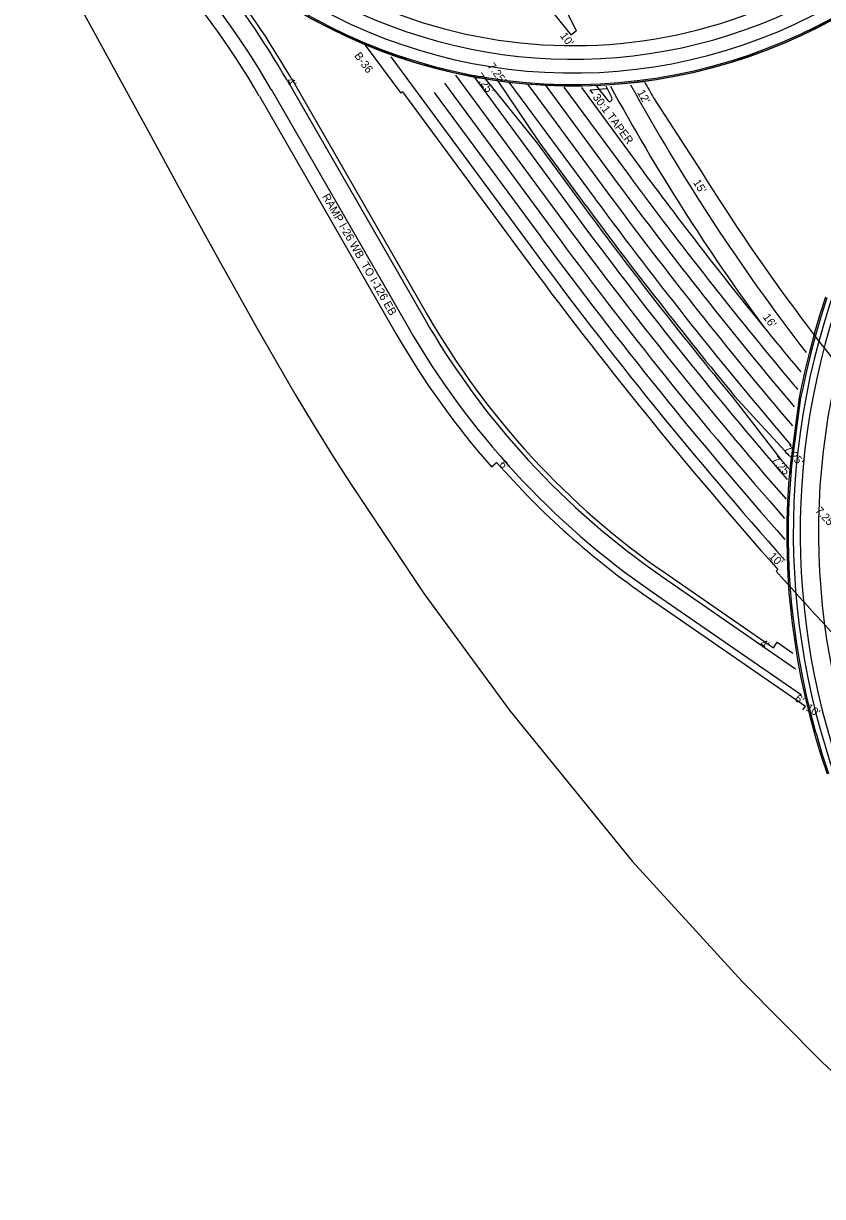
# Model space of a CAD drawing. Extents: x -5665 to 1997148, y 4 to 812485.
# Drawn here: x 1970730 to 1971429, y 795072 to 796097 of the extents above; entities that cross this region are included whole.
import ezdxf

# ---------------------------------------------------------------- set-up
doc = ezdxf.new("R2010")
doc.units = 0
for name, color, linetype in [('BR_CONCRETE', 7, 'Continuous'), ('RD_EX_RailRoad', 7, 'Continuous'), ('RD_PD_ALT1_TrvlWay', 7, 'Continuous'), ('RD_PD_Final_LnLine', 7, 'Continuous'), ('RD_PD_MedBWall', 7, 'Continuous'), ('RD_PD_PaveShd', 7, 'Continuous'), ('RD_SHT_TX', 7, 'Continuous')]:
    doc.layers.add(name, color=color, linetype=linetype)

msp = doc.modelspace()

# ---------------------------------------------------------------- linework, layer by layer
at = {"layer": 'BR_CONCRETE'}
for points in [[(1971431.6, 795857.9), (1971426.5, 795842), (1971421.8, 795826), (1971417.5, 795809.9), (1971413.6, 795793.7), (1971410.1, 795777.4), (1971408.6, 795770.1), (1971400.6, 795710.7), (1971399.3, 795694.8), (1971398.4, 795678.8), (1971397.8, 795662.9), (1971397.7, 795647), (1971398, 795631), (1971398.7, 795615.1), (1971399.7, 795599.2), (1971400.7, 795588.6), (1971402.5, 795572.7), (1971404.7, 795556.8), (1971407.2, 795541), (1971410.2, 795525.2), (1971413.6, 795509.5), (1971417.3, 795494), (1971421.5, 795478.5), (1971422.6, 795474.3), (1971427.6, 795457.7), (1971433, 795441.2)], [(1971432.8, 795857.4), (1971427.8, 795841.6), (1971423.1, 795825.6), (1971418.8, 795809.5), (1971414.9, 795793.4), (1971411.4, 795777.1), (1971409.9, 795769.9), (1971401.9, 795710.5), (1971400.6, 795694.7), (1971399.7, 795678.8), (1971399.1, 795662.9), (1971399, 795647), (1971399.3, 795631), (1971400, 795615.1), (1971401, 795599.3), (1971402, 795588.7), (1971403.8, 795572.8), (1971405.9, 795557), (1971408.5, 795541.2), (1971411.5, 795525.5), (1971414.8, 795509.8), (1971418.6, 795494.3), (1971422.7, 795478.8), (1971423.9, 795474.7), (1971428.8, 795458.1), (1971434.2, 795441.6)]]:
    msp.add_lwpolyline(points, dxfattribs=at)
for radius, start in [(473.1, 234.9869), (472, 234.9869), (473.3, 235.2092)]:
    msp.add_arc((1971210.8, 796516), radius, start, 298.9233, dxfattribs=at)
at = {"layer": 'RD_EX_RailRoad'}
msp.add_lwpolyline([(1970768.6, 796133), (1970840.2, 796002.2), (1970871.3, 795945), (1970902.8, 795888.1), (1970934.6, 795831.3), (1970952.2, 795800.2), (1970967.8, 795773.4), (1970983.8, 795746.9), (1971000.1, 795720.5), (1971015.2, 795696.8), (1971080.6, 795598.9), (1971156, 795496.1), (1971262.7, 795364.9), (1971358.8, 795259.6), (1971428.3, 795189.4), (1971512.5, 795110.8), (1971575.1, 795055.9)], dxfattribs=at)
at = {"layer": 'RD_PD_ALT1_TrvlWay'}
for p, q in [((1971051.6, 796068.3), (1971173.9, 795902.4)), ((1971124.1, 796050.9), (1971212.6, 795930.8)), ((1970947.1, 796039.8), (1971066.5, 795832.3)), ((1970960.9, 796047.7), (1971080.4, 795840.3)), ((1971154.9, 796046.1), (1971230.3, 795943.9)), ((1971218.2, 796041.3), (1971268.9, 795972.4)), ((1971231.5, 796042.4), (1971241.3, 796030)), ((1971239.7, 796042.8), (1971244.7, 796032.2)), ((1971289.1, 795613.6), (1971405.5, 795533.2)), ((1971280, 795600.5), (1971410.6, 795510.2))]:
    msp.add_line(p, q, dxfattribs=at)
for centre, radius, start, end in [((1970326.5, 795682.5), 716, 29.9281, 54.9869), ((1971210.8, 796516), 438, 216.3977, 298.9233), ((1970326.5, 795682.5), 732, 29.9281, 48.9944), ((1971210.8, 796516), 462, 234.9869, 298.9233), ((1972855.7, 796921.2), 1836, 208.5881, 216.4039), ((1972855.7, 796921.2), 1820, 208.8218, 217.6449), ((1971243, 796031.2), 2, 216.3977, 28.8919), ((1974296, 798203.9), 3760.7, 216.3977, 219.1113), ((1974296, 798203.9), 3808.7, 216.3977, 220.5407), ((1974296, 798203.9), 3830.7, 216.3977, 220.845), ((1972046.2, 795652), 636.6, 156.2104, 245.7151), ((1974296, 798203.9), 3878.7, 216.3977, 221.6129), ((1972046.2, 795652), 620.6, 156.2104, 245.7151), ((1971687, 796189.5), 700, 209.9281, 235.3566), ((1971687, 796189.5), 716, 209.9281, 235.3566)]:
    msp.add_arc(centre, radius, start, end, dxfattribs=at)
at = {"layer": 'RD_PD_Final_LnLine'}
for p, q in [((1971108.2, 796052.2), (1971202.9, 795923.7)), ((1971098.5, 796045.1), (1971193.3, 795916.6)), ((1971171.5, 796043.9), (1971240, 795951)), ((1971186.5, 796043.7), (1971249.6, 795958.1)), ((1971203, 796041.6), (1971259.3, 795965.3)), ((1971089.6, 796036.9), (1971183.6, 795909.5))]:
    msp.add_line(p, q, dxfattribs=at)
for centre, radius, start, end in [((1971210.8, 796516), 450, 239.8879, 298.9233), ((1974296, 798203.9), 3784.7, 216.3977, 220.1755), ((1974296, 798203.9), 3772.7, 216.3977, 219.8973), ((1974296, 798203.9), 3796.7, 216.3977, 220.3528), ((1974296, 798203.9), 3854.7, 216.3977, 221.2048), ((1974296, 798203.9), 3842.7, 216.3977, 221.0293), ((1974296, 798203.9), 3866.7, 216.3977, 221.4111), ((1974296, 798203.9), 3760.7, 219.1113, 219.8764), ((1974296, 798203.9), 3772.7, 219.8973, 220.0312)]:
    msp.add_arc(centre, radius, start, end, dxfattribs=at)
at = {"layer": 'RD_PD_MedBWall'}
for p, q in [((1971144.2, 796048.5), (1971181.1, 795993.8)), ((1971138.1, 796044.1), (1971179.5, 795992.6)), ((1971179.5, 795992.6), (1971220.6, 795936.8)), ((1971181.1, 795993.8), (1971222.2, 795938)), ((1971352.2, 795771.5), (1971396.1, 795723.6)), ((1971350.7, 795770.2), (1971390.4, 795718.7))]:
    msp.add_line(p, q, dxfattribs=at)
for radius, end in [(3820.7, 219.5667), (3818.7, 219.5661)]:
    msp.add_arc((1974296, 798203.9), radius, 216.3977, end, dxfattribs=at)
at = {"layer": 'RD_PD_PaveShd'}
for p, q in [((1971063.2, 796271.6), (1971208.9, 796087.3)), ((1971208.9, 796087.3), (1971213.7, 796090.8)), ((1971029.2, 796078.4), (1971060.3, 796036.3)), ((1970964.4, 796049.7), (1971083.8, 795842.3)), ((1971138.1, 796044.1), (1971133.7, 796050.1)), ((1970936.7, 796033.8), (1971056.1, 795826.3)), ((1971061.9, 796037.5), (1971060.3, 796036.3)), ((1971061.9, 796037.5), (1971165.9, 795896.4)), ((1971281.2, 796032.4), (1971323.1, 795967.7)), ((1971181.1, 795993.8), (1971222.2, 795938)), ((1971139.6, 795709.6), (1971144.1, 795713.6)), ((1971389.9, 795620), (1971388.5, 795618.6)), ((1971291.4, 795616.9), (1971386.1, 795551.5)), ((1971276.6, 795595.5), (1971414.1, 795500.5)), ((1971386.1, 795551.5), (1971389.5, 795556.4)), ((1971389.5, 795556.4), (1971403.2, 795546.9)), ((1971411.8, 795497.2), (1971414.1, 795500.5))]:
    msp.add_line(p, q, dxfattribs=at)
for centre, radius, start, end in [((1970326.5, 795682.5), 704, 29.9281, 54.9869), ((1970326.5, 795682.5), 736, 29.9281, 40.3148), ((1971210.8, 796516), 472, 234.9869, 298.9233), ((1971210.8, 796516), 472, 234.9869, 298.9233), ((1972855.7, 796921.2), 1840, 205.7611, 206.8263), ((1972855.7, 796921.2), 1808, 208.9372, 209.4454), ((1972855.7, 796921.2), 1805, 211.8865, 221.6884), ((1972046.2, 795652), 642.6, 156.2104, 245.7151), ((1974296, 798203.9), 3888.7, 216.3977, 221.6415), ((1971687, 796189.5), 696, 209.9281, 235.3566), ((1971687, 796189.5), 728, 209.9281, 221.2407), ((1974296, 798203.9), 3816, 220.5414, 220.6322), ((1971687, 796189.5), 722, 221.2407, 235.3566), ((1974296, 798203.9), 3823.5, 220.5417, 220.7294), ((1974296, 798203.9), 3890.7, 221.6429, 226.413)]:
    msp.add_arc(centre, radius, start, end, dxfattribs=at)
at = {"layer": 'RD_SHT_TX'}
for p, q in [((1971225.9, 796039.2), (1971240.8, 796040.6)), ((1971228.3, 796036), (1971225.9, 796039.2))]:
    msp.add_line(p, q, dxfattribs=at)

# ---------------------------------------------------------------- texts
for s, rotation, p in [("10'", 306.3992, (1971199.2, 796086.5)), ('B-36', 306.3976, (1971019.3, 796069.1)), ("7.25'", 306.2638, (1971135.8, 796060)), ("4'", 300.3676, (1970960, 796047.3)), ("7.25'", 306.2638, (1971125.1, 796051)), ("12'", 299.265, (1971266.7, 796037.1)), ('30:1 TAPER', 306.5095, (1971227.7, 796032.8)), ("15'", 301.844, (1971315.6, 795958.4)), (' RAMP I-26 WB  TO I-126 EB', 299.6469, (1970990.1, 795948.4)), ("16'", 306.3501, (1971376.5, 795840.5)), ("7.25'", 312.7111, (1971383.8, 795715.3)), ("7.25'", 312.7111, (1971394.6, 795724.9)), ("6'", 310.1999, (1971146, 795711.6)), ("7.25'", 312.7111, (1971422.2, 795671)), ("10'", 315.2852, (1971381.7, 795630.8)), ("4'", 326.2427, (1971373.6, 795553.7)), ("6'", 322.6442, (1971404.1, 795505.8)), ("10'", 326.4769, (1971413.8, 795497.4))]:
    msp.add_text(s, height=7, rotation=rotation, dxfattribs=at).set_placement(p)

doc.saveas('drawing.dxf')
